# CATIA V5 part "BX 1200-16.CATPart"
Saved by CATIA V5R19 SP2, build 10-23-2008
Part number: BX 1200-16
Bounding box of the stored display mesh (mm): x -59.975 to 59.975, y -59.975 to 59.975, z 0 to 126
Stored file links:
  C:\Users\Bora\Desktop\3D Katı model\BX serisi\BX 1200\BX 1200-16.CATPart
  C:\Program Files\Dassault Systemes\B19\intel_a\reffiles\standard\MetricThickPitch.txt
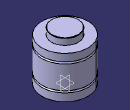
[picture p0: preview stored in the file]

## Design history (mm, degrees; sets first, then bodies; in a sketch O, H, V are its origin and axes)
Body1 (main body)
  Sketch1 on yz-plane, origin (0, 0, 0), H (0, 1, 0), V (0, 0, 1)
    point P1 (60, 85)
    point P2 (60, 90)
    arc A1 centre (60, 87.5) radius 2.5 from (60, 90) to (60, 85) ccw
    point P3 (60, 20)
    point P4 (60, 25)
    arc A2 centre (60, 22.5) radius 2.5 from (60, 25) to (60, 20) ccw
    point P5 (60, 90)
    line L1 (60, 109) -> (60, 90)
    point P8 (35, 125)
    line L2 (35, 125) -> (35, 109)
    point P10 (35, 125)
    arc A3 centre (34, 125) radius 1 from (35, 125) to (34, 126) ccw
    point P11 (60, 25)
    point P12 (60, 85)
    line L3 (60, 85) -> (60, 25)
    point P14 (60, 20)
    line L4 (60, 20) -> (60, 0)
    line L5 (34, 126) -> (0, 126)
    point P15 (0, 126)
    line L6 (35, 109) -> (60, 109)
    line L7 (60, 0) -> (0, 0)
    tangency: L5 A3
    coincidence: P15 V, P1 P12, P2 P5, P3 P14, P4 P11, P8 P10
    horizontal: L6 H, L7 H
  Shaft1: profile Sketch1, axis Sketch1.V, angle 360
  Sketch2 on face of Shaft1 from Sketch1.L7, origin (0, 0, 0), H (1, 0, 0), V (0, -1, 0)
    point P1 (32.5, 0)
    distance V P1 = 32.5
  Hole1: placed by Sketch2, at (32.5, 0, 0) direction (0, 0, 1), diameter 8.376, depth 10, threaded "M10", thread diameter 10, thread depth 10, pitch 1.5
  CircPattern1: of Hole1, instances 4, angular step 90, axis from xy-plane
